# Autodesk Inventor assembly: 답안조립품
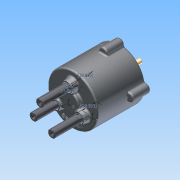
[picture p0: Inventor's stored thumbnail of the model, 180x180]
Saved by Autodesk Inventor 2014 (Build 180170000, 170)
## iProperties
Created: 2015-09
Part Number: 답안조립품
Document SubType Name: Assembly
Designer: study
Author: study
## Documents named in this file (14)
- C:\Users\study\Desktop\350916V1025\답안조립품.iam
- C:\Users\study\Desktop\350916V1025\몸체.ipt
- C:\Users\study\Desktop\350916V1025\M5x0.8x20.ipt
- C:\Users\study\Desktop\350916V1025\오일실.ipt
- C:\Users\study\Desktop\350916V1025\커버.ipt
- C:\Users\study\Desktop\350916V1025\멈춤링 10 x 1.ipt
- C:\Users\study\Desktop\350916V1025\멈춤링 22 x 1.2.ipt
- C:\Users\study\Desktop\350916V1025\메인 축.ipt
- C:\Users\study\Desktop\350916V1025\베어링 NA 4900.ipt
- C:\Users\study\Desktop\350916V1025\슬라이드 축.ipt
- C:\Users\study\Desktop\350916V1025\판캠.ipt
- C:\Users\study\Desktop\350916V1025\가변 스프링-01.ipt
- C:\Users\study\Desktop\350916V1025\가변 스프링-02.ipt
- C:\Users\study\Desktop\350916V1025\가변 스프링-03.ipt
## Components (7 placed, 4 different names)
1. 가변 스프링-01:1
2. 가변 스프링-02:1
3. 가변 스프링-03:1
4. M5x0.8x20:1
5. M5x0.8x20:2
6. M5x0.8x20:3
7. M5x0.8x20:4
